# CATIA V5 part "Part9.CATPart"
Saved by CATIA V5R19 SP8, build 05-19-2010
Part number: Carter
Bounding box of the stored display mesh (mm): x 0 to 240, y 713.534 to 1293.443, z -214.067 to 97.363
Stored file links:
  G:\EU_thinkMotion\CFAO_2010\MMS_groupe1\MMS_groupe1\OK\ppiault\piault\piault_cfao\Part9.CATPart
  D:\Catia\Finaltest.CATProduct
  G:\EU_thinkMotion\CFAO_2010\MMS_groupe1\MMS_groupe1\OK\ppiault\piault\piault_cfao\Part1.CATPart
  G:\Catia Projet\CFAO2\Product2.CATProduct
  G:\EU_thinkMotion\CFAO_2010\MMS_groupe1\MMS_groupe1\OK\ppiault\piault\piault_cfao\Part2.CATPart
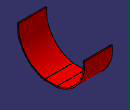
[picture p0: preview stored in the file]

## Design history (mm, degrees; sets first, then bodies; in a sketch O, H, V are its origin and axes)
Parameters
  epaisseur_tole = 10 mm
External parameters (linked from other documents)
  External.DiametreRabatteur = 400 mm
  External.Epaisseur = 5 mm
  External.Longueur_Support = 280 mm
  External.haut_axe = 195 mm
  External.bas_axe = 255 mm
Set1
  Point1: linked copy from another document
Body1 (main body)
  Sketch1 on yz-plane, origin (0, 0, 0), H (0, 1, 0), V (0, 0, 1)
    arc A1 centre (1003.4886, 70.9331) radius 280 from (724.7388, 97.3634) to (950.8103, -204.0669) ccw
    point P1 (1003.4886, 70.9331)
    arc A2 centre (1003.4886, 70.9331) radius 290 from (714.6955, 97.3634) to (949.8696, -214.0669) ccw
    point P2 (1003.4886, 70.9331)
    line L1 (714.6955, 97.3634) -> (724.7388, 97.3634)
    point P5 (1282.2384, 97.3634)
    line L2 (1282.2384, 97.3634) -> (1292.2817, 97.3634)
    line L3 (950.8103, -204.0669) -> (1056.1669, -204.0669)
    line L4 (949.8696, -214.0669) -> (1057.1076, -214.0669)
    arc A3 centre (1003.4886, 70.9331) radius 290 from (1057.1076, -214.0669) to (1292.2817, 97.3634) ccw
    arc A4 centre (1003.4886, 70.9331) radius 280 from (1056.1669, -204.0669) to (1282.2384, 97.3634) ccw
    reference projected point E1 (1003.4886, 70.9331) from Point1
    distance A1 A2 = 10 {= epaisseur_tole}
    distance L4 L3 = 10 {= 2*External.Epaisseur}
    radius A1 = 280 {= 0.7*External.DiametreRabatteur}
    distance E1 L4 = 285 {= External.Longueur_Support +External.Epaisseur}
    coincidence: P1 P2, L1 P5, L1 L2, A2 A3, A1 A4
    horizontal: L1 H, L2 H, L3 H, L4 H
  Pad1: profile Sketch1, direction (1, 0, 0), length 240 {= (170/195)*External.haut_axe  +(70/255)*External.bas_axe}
  Fillet1: radius 10, on edge [face of Pad1 from Sketch1.A3 | face of Pad1 from Sketch1.L4]; edge [face of Pad1 from Sketch1.L4 | face of Pad1 from Sketch1.A2]; edge [face of Pad1 from Sketch1.L3 | face of Pad1 from Sketch1.A4]; edge [face of Pad1 from Sketch1.A1 | face of Pad1 from Sketch1.L3]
